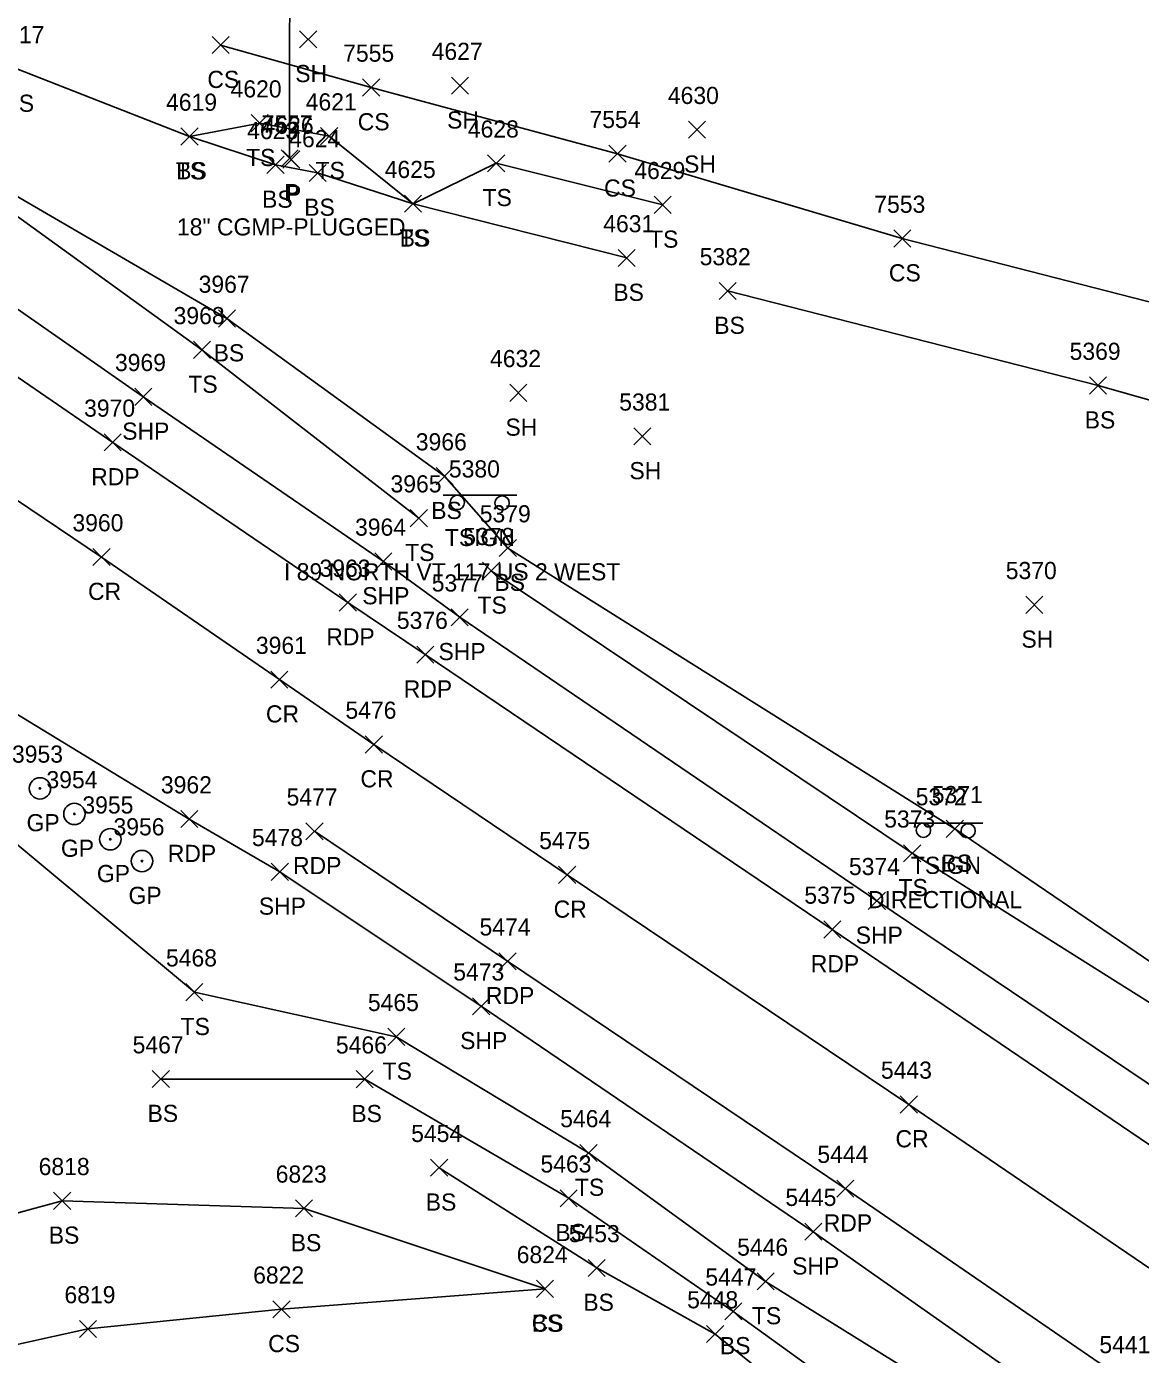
# Model space of a CAD drawing. Extents: x 1505656 to 1508446, y 700805 to 703031.
# Drawn here: x 1507341.1 to 1507471, y 701441 to 701595.9 of the extents above; entities that cross this region are included whole.
import ezdxf

# ---------------------------------------------------------------- set-up
doc = ezdxf.new("R2010")
doc.units = 0
for name, color, linetype in [('D_A', 7, 'Continuous'), ('D_C', 7, 'Continuous'), ('D_I', 7, 'Continuous'), ('D_TIC', 7, 'Continuous'), ('DCP', 7, 'Continuous'), ('L_A', 7, 'Continuous'), ('L_I', 7, 'Continuous'), ('L_TIC', 7, 'Continuous'), ('LELB', 7, 'Continuous'), ('P_A', 7, 'Continuous'), ('P_I', 7, 'Continuous'), ('P_TIC', 7, 'Continuous'), ('PET', 7, 'Continuous'), ('PRC', 7, 'Continuous'), ('PSP', 7, 'Continuous'), ('R_A', 7, 'Continuous'), ('R_I', 7, 'Continuous'), ('RGP', 7, 'Continuous'), ('S_A', 7, 'Continuous'), ('S_C', 7, 'Continuous'), ('S_I', 7, 'Continuous'), ('SSGN', 7, 'Continuous')]:
    doc.layers.add(name, color=color, linetype=linetype)

msp = doc.modelspace()

# ---------------------------------------------------------------- linework, layer by layer
at = {"layer": 'D_TIC'}
for points in [[(1507370.79, 701579.54), (1507372.79, 701581.54)], [(1507372.79, 701579.54), (1507370.79, 701581.54)], [(1507371, 701579.4), (1507373, 701581.4)], [(1507373, 701579.4), (1507371, 701581.4)]]:
    msp.add_lwpolyline(points, dxfattribs=at)
at = {"layer": 'DCP'}
msp.add_lwpolyline([(1507371.87, 701643.87), (1507371.79, 701580.54)], dxfattribs=at)
at = {"layer": 'L_TIC'}
for points in [[(1507372.96, 701593.42), (1507374.96, 701595.42)], [(1507374.96, 701593.42), (1507372.96, 701595.42)], [(1507362.75, 701592.74), (1507364.75, 701594.74)], [(1507364.75, 701592.74), (1507362.75, 701594.74)], [(1507380.3, 701587.8), (1507382.3, 701589.8)], [(1507382.3, 701587.8), (1507380.3, 701589.8)], [(1507390.67, 701588.01), (1507392.67, 701590.01)], [(1507392.67, 701588.01), (1507390.67, 701590.01)], [(1507367.31, 701583.63), (1507369.31, 701585.63)], [(1507369.31, 701583.63), (1507367.31, 701585.63)], [(1507359.12, 701582.08), (1507361.12, 701584.08)], [(1507361.12, 701582.08), (1507359.12, 701584.08)], [(1507359.12, 701582.08), (1507361.12, 701584.08)], [(1507361.12, 701582.08), (1507359.12, 701584.08)], [(1507375.41, 701582.12), (1507377.41, 701584.12)], [(1507377.41, 701582.12), (1507375.41, 701584.12)], [(1507418.31, 701582.87), (1507420.31, 701584.87)], [(1507420.31, 701582.87), (1507418.31, 701584.87)], [(1507394.89, 701578.96), (1507396.89, 701580.96)], [(1507396.89, 701578.96), (1507394.89, 701580.96)], [(1507409.03, 701580.07), (1507411.03, 701582.07)], [(1507411.03, 701580.07), (1507409.03, 701582.07)], [(1507369.14, 701578.77), (1507371.14, 701580.77)], [(1507371.14, 701578.77), (1507369.14, 701580.77)], [(1507374.06, 701577.83), (1507376.06, 701579.83)], [(1507376.06, 701577.83), (1507374.06, 701579.83)], [(1507385.19, 701574.24), (1507387.19, 701576.24)], [(1507387.19, 701574.24), (1507385.19, 701576.24)], [(1507385.19, 701574.24), (1507387.19, 701576.24)], [(1507387.19, 701574.24), (1507385.19, 701576.24)], [(1507414.31, 701574.11), (1507416.31, 701576.11)], [(1507416.31, 701574.11), (1507414.31, 701576.11)], [(1507442.25, 701570.18), (1507444.25, 701572.18)], [(1507444.25, 701570.18), (1507442.25, 701572.18)], [(1507410.11, 701567.91), (1507412.11, 701569.91)], [(1507412.11, 701567.91), (1507410.11, 701569.91)], [(1507421.88, 701564.06), (1507423.88, 701566.06)], [(1507423.88, 701564.06), (1507421.88, 701566.06)], [(1507363.48, 701560.85), (1507365.48, 701562.85)], [(1507365.48, 701560.85), (1507363.48, 701562.85)], [(1507360.57, 701557.19), (1507362.57, 701559.19)], [(1507362.57, 701557.19), (1507360.57, 701559.19)], [(1507465.09, 701553.03), (1507467.09, 701555.03)], [(1507467.09, 701553.03), (1507465.09, 701555.03)], [(1507397.48, 701552.18), (1507399.48, 701554.18)], [(1507399.48, 701552.18), (1507397.48, 701554.18)], [(1507411.94, 701547.11), (1507413.94, 701549.11)], [(1507413.94, 701547.11), (1507411.94, 701549.11)], [(1507388.87, 701542.47), (1507390.87, 701544.47)], [(1507390.87, 701542.47), (1507388.87, 701544.47)], [(1507385.87, 701537.57), (1507387.87, 701539.57)], [(1507387.87, 701537.57), (1507385.87, 701539.57)], [(1507396.24, 701534.08), (1507398.24, 701536.08)], [(1507398.24, 701534.08), (1507396.24, 701536.08)], [(1507394.3, 701531.43), (1507396.3, 701533.43)], [(1507396.3, 701531.43), (1507394.3, 701533.43)], [(1507457.66, 701527.46), (1507459.66, 701529.46)], [(1507459.66, 701527.46), (1507457.66, 701529.46)], [(1507448.38, 701501.33), (1507450.38, 701503.33)], [(1507450.38, 701501.33), (1507448.38, 701503.33)], [(1507443.4, 701498.48), (1507445.4, 701500.48)], [(1507445.4, 701498.48), (1507443.4, 701500.48)], [(1507359.68, 701482.28), (1507361.68, 701484.28)], [(1507361.68, 701482.28), (1507359.68, 701484.28)], [(1507383.23, 701477.08), (1507385.23, 701479.08)], [(1507385.23, 701477.08), (1507383.23, 701479.08)], [(1507355.78, 701472.15), (1507357.78, 701474.15)], [(1507357.78, 701472.15), (1507355.78, 701474.15)], [(1507379.55, 701472.13), (1507381.55, 701474.13)], [(1507381.55, 701472.13), (1507379.55, 701474.13)], [(1507405.66, 701463.53), (1507407.66, 701465.53)], [(1507407.66, 701463.53), (1507405.66, 701465.53)], [(1507388.23, 701461.81), (1507390.23, 701463.81)], [(1507390.23, 701461.81), (1507388.23, 701463.81)], [(1507403.35, 701458.25), (1507405.35, 701460.25)], [(1507405.35, 701458.25), (1507403.35, 701460.25)], [(1507344.26, 701457.95), (1507346.26, 701459.95)], [(1507346.26, 701457.95), (1507344.26, 701459.95)], [(1507372.48, 701457.07), (1507374.48, 701459.07)], [(1507374.48, 701457.07), (1507372.48, 701459.07)], [(1507406.61, 701450.12), (1507408.61, 701452.12)], [(1507408.61, 701450.12), (1507406.61, 701452.12)], [(1507400.59, 701447.68), (1507402.59, 701449.68)], [(1507402.59, 701447.68), (1507400.59, 701449.68)], [(1507400.59, 701447.68), (1507402.59, 701449.68)], [(1507402.59, 701447.68), (1507400.59, 701449.68)], [(1507426.31, 701448.55), (1507428.31, 701450.55)], [(1507428.31, 701448.55), (1507426.31, 701450.55)], [(1507369.84, 701445.3), (1507371.84, 701447.3)], [(1507371.84, 701445.3), (1507369.84, 701447.3)], [(1507422.54, 701445.06), (1507424.54, 701447.06)], [(1507424.54, 701445.06), (1507422.54, 701447.06)], [(1507347.27, 701443), (1507349.27, 701445)], [(1507349.27, 701443), (1507347.27, 701445)], [(1507420.42, 701442.41), (1507422.42, 701444.41)], [(1507422.42, 701442.41), (1507420.42, 701444.41)]]:
    msp.add_lwpolyline(points, dxfattribs=at)
at = {"layer": 'LELB'}
for points in [[(1507389.87, 701543.47), (1507364.48, 701561.85), (1507301.81, 701598.33), (1507262.96, 701621.17), (1507238.69, 701635.33), (1507228.62, 701642.18), (1507195.21, 701666.36), (1507195.45, 701673.67), (1507195.45, 701673.62), (1507166.37, 701693.97), (1507153.7, 701702.61), (1507143.46, 701707.63), (1507119.44, 701724.95), (1507096.28, 701741.3), (1507098.84, 701745.06), (1507084.55, 701753.38), (1507076.37, 701753.77)], [(1507247.4, 701638.91), (1507254.77, 701631.75), (1507267.97, 701626.49), (1507283.55, 701614.76), (1507308.22, 701603.82), (1507321.52, 701597.53), (1507339.98, 701590.96), (1507360.12, 701583.08), (1507370.14, 701579.77), (1507375.06, 701578.83), (1507386.19, 701575.24), (1507411.11, 701568.91)], [(1507386.87, 701538.57), (1507361.57, 701558.19), (1507324.01, 701585.32), (1507299.55, 701594.54), (1507261.37, 701618.9), (1507238.69, 701635.33)], [(1508002.64, 701414.99), (1507979.81, 701421.48), (1507944.12, 701429.96), (1507890.75, 701447.74), (1507838.58, 701464.8), (1507785.46, 701481.02), (1507746.69, 701489.76), (1507701.55, 701503.96), (1507692.53, 701505.99), (1507687.4, 701507.46), (1507675.9, 701505.41), (1507637.25, 701514.14), (1507591.55, 701528.66), (1507550.69, 701540.13), (1507511.03, 701552.01), (1507480.52, 701561.6), (1507443.25, 701571.18), (1507410.03, 701581.07), (1507381.3, 701588.8), (1507363.75, 701593.74)], [(1507360.12, 701583.08), (1507368.31, 701584.63), (1507376.41, 701583.12), (1507386.19, 701575.24), (1507395.89, 701579.96), (1507415.31, 701575.11)], [(1507494.24, 701475.49), (1507485.48, 701485.12), (1507482.34, 701502.12), (1507485.56, 701510.11), (1507495.72, 701531.95), (1507503.53, 701543.43), (1507466.09, 701554.03), (1507422.88, 701565.06)], [(1507397.24, 701535.08), (1507389.87, 701543.47)], [(1507596.81, 701404.28), (1507581.31, 701416.71), (1507546.65, 701439.08), (1507526.39, 701451.36), (1507494.24, 701475.49), (1507483.92, 701478.85), (1507449.38, 701502.33), (1507397.24, 701535.08)], [(1507585.56, 701401.05), (1507575.59, 701409.05), (1507541.66, 701431.82), (1507522.44, 701445.53), (1507489.85, 701469.54), (1507483.43, 701474.91), (1507444.4, 701499.48), (1507395.3, 701532.43)], [(1507331.15, 701507.85), (1507360.68, 701483.28)], [(1507556.64, 701327.28), (1507557.61, 701343.99), (1507554.26, 701358.96), (1507537.42, 701375.15), (1507498.82, 701402.26), (1507464.49, 701426.4), (1507427.31, 701449.55), (1507406.66, 701464.53), (1507384.23, 701478.08), (1507360.68, 701483.28)], [(1507257.2, 701477.1), (1507295.53, 701466.28), (1507314.2, 701450.53), (1507345.26, 701458.95), (1507373.48, 701458.07), (1507401.59, 701448.68)], [(1507552.22, 701329.86), (1507547.62, 701348.23), (1507546.96, 701358.62), (1507528.89, 701372.8), (1507497.02, 701400), (1507459.73, 701419.9), (1507423.54, 701446.06), (1507404.35, 701459.25), (1507380.55, 701473.13), (1507356.78, 701473.15)], [(1507253.51, 701468.63), (1507288.66, 701454.6), (1507310.43, 701435.66), (1507348.27, 701444), (1507370.84, 701446.3), (1507401.59, 701448.68)], [(1507544.85, 701333.56), (1507537.16, 701349.93), (1507537.38, 701358.92), (1507523.47, 701367.02), (1507491.66, 701393.21), (1507456.99, 701414.76), (1507421.42, 701443.41), (1507407.61, 701451.12), (1507389.23, 701462.81)]]:
    msp.add_lwpolyline(points, dxfattribs=at)
at = {"layer": 'P_TIC'}
for points in [[(1507353.73, 701551.72), (1507355.73, 701553.72)], [(1507355.73, 701551.72), (1507353.73, 701553.72)], [(1507350.16, 701546.4), (1507352.16, 701548.4)], [(1507352.16, 701546.4), (1507350.16, 701548.4)], [(1507348.85, 701533.03), (1507350.85, 701535.03)], [(1507350.85, 701533.03), (1507348.85, 701535.03)], [(1507381.73, 701532.52), (1507383.73, 701534.52)], [(1507383.73, 701532.52), (1507381.73, 701534.52)], [(1507377.59, 701527.73), (1507379.59, 701529.73)], [(1507379.59, 701527.73), (1507377.59, 701529.73)], [(1507390.63, 701526.01), (1507392.63, 701528.01)], [(1507392.63, 701526.01), (1507390.63, 701528.01)], [(1507386.62, 701521.65), (1507388.62, 701523.65)], [(1507388.62, 701521.65), (1507386.62, 701523.65)], [(1507369.6, 701518.74), (1507371.6, 701520.74)], [(1507371.6, 701518.74), (1507369.6, 701520.74)], [(1507380.62, 701511.17), (1507382.62, 701513.17)], [(1507382.62, 701511.17), (1507380.62, 701513.17)], [(1507359.09, 701502.47), (1507361.09, 701504.47)], [(1507361.09, 701502.47), (1507359.09, 701504.47)], [(1507373.7, 701501.05), (1507375.7, 701503.05)], [(1507375.7, 701501.05), (1507373.7, 701503.05)], [(1507369.66, 701496.32), (1507371.66, 701498.32)], [(1507371.66, 701496.32), (1507369.66, 701498.32)], [(1507403.16, 701495.97), (1507405.16, 701497.97)], [(1507405.16, 701495.97), (1507403.16, 701497.97)], [(1507439.29, 701492.94), (1507441.29, 701494.94)], [(1507441.29, 701492.94), (1507439.29, 701494.94)], [(1507434.09, 701489.6), (1507436.09, 701491.6)], [(1507436.09, 701489.6), (1507434.09, 701491.6)], [(1507396.2, 701485.89), (1507398.2, 701487.89)], [(1507398.2, 701485.89), (1507396.2, 701487.89)], [(1507393.14, 701480.64), (1507395.14, 701482.64)], [(1507395.14, 701480.64), (1507393.14, 701482.64)], [(1507443.02, 701469.19), (1507445.02, 701471.19)], [(1507445.02, 701469.19), (1507443.02, 701471.19)], [(1507435.61, 701459.37), (1507437.61, 701461.37)], [(1507437.61, 701459.37), (1507435.61, 701461.37)], [(1507431.87, 701454.35), (1507433.87, 701456.35)], [(1507433.87, 701454.35), (1507431.87, 701456.35)]]:
    msp.add_lwpolyline(points, dxfattribs=at)
at = {"layer": 'PET'}
for points in [[(1507378.59, 701528.73), (1507351.16, 701547.4), (1507314.88, 701572.26), (1507294.11, 701586.22), (1507256.28, 701612.27), (1507223.68, 701635.26), (1507191.52, 701659.04), (1507185.41, 701663.24), (1507156.11, 701681.55), (1507130.98, 701696.87), (1507096.16, 701719.91), (1507064.32, 701737.66), (1507038.74, 701752.58), (1507011.47, 701766.55), (1506986.91, 701777.55), (1506973.48, 701783.54), (1506938.47, 701797.09), (1506905.53, 701808.93), (1506877.58, 701817.04), (1506846.41, 701824.78), (1506827.4, 701828.82), (1506804.26, 701834.04), (1506782.21, 701837.88), (1506762.06, 701842.49)], [(1507210, 701607.35), (1507255.64, 701576.09), (1507286.41, 701554.16), (1507313.14, 701536.08), (1507337.33, 701517.31), (1507360.09, 701503.47)], [(1507387.62, 701522.65), (1507378.59, 701528.73)], [(1507628.51, 701359.69), (1507604.05, 701376.49), (1507573.51, 701397.18), (1507535.4, 701422.88), (1507481.89, 701458.82), (1507435.09, 701490.6), (1507387.62, 701522.65)], [(1507650.58, 701314.23), (1507605.27, 701346.09), (1507547.72, 701383.86), (1507511.59, 701409.01), (1507468.93, 701438.18), (1507436.61, 701460.37), (1507397.2, 701486.89), (1507374.7, 701502.05)]]:
    msp.add_lwpolyline(points, dxfattribs=at)
at = {"layer": 'PRC'}
for points in [[(1507221.62, 701620.55), (1507265.06, 701591.23), (1507297.41, 701569.41), (1507322.82, 701552.21), (1507349.85, 701534.03), (1507370.6, 701519.74)], [(1507381.62, 701512.17), (1507370.6, 701519.74)], [(1507656.71, 701325.12), (1507611.54, 701355.7), (1507570.54, 701383.97), (1507541.91, 701403.48), (1507511.11, 701424.43), (1507476, 701448.42), (1507444.02, 701470.19), (1507404.16, 701496.97), (1507381.62, 701512.17)]]:
    msp.add_lwpolyline(points, dxfattribs=at)
at = {"layer": 'PSP'}
for points in [[(1507382.73, 701533.52), (1507354.73, 701552.72), (1507319.48, 701577.3), (1507297.42, 701590.8), (1507259.58, 701616.5), (1507227.21, 701639.99), (1507194.31, 701663.43), (1507160.97, 701687.92), (1507137.4, 701705.45), (1507106.21, 701729.57), (1507075.31, 701752.35), (1507059.92, 701763.53), (1507033.38, 701782.57), (1507002.26, 701805.46), (1506985.6, 701817.32), (1506980.95, 701818.44), (1506978.16, 701819.92), (1506965.68, 701828.93)], [(1507391.63, 701527.01), (1507382.73, 701533.52)], [(1507630.66, 701364.45), (1507607.41, 701380.86), (1507575.86, 701401.66), (1507537.87, 701427.72), (1507485.39, 701463.56), (1507440.29, 701493.94), (1507391.63, 701527.01)], [(1507370.66, 701497.32), (1507360.09, 701503.47)], [(1507544.33, 701378.59), (1507503.06, 701407.32), (1507465.55, 701432.37), (1507432.87, 701455.35), (1507394.14, 701481.64), (1507370.66, 701497.32)]]:
    msp.add_lwpolyline(points, dxfattribs=at)
at = {"layer": 'RGP'}
for p, q in [((1507342.67, 701507.05), (1507342.67, 701507.05)), ((1507346.69, 701504.07), (1507346.69, 701504.07)), ((1507350.88, 701501.12), (1507350.88, 701501.12)), ((1507354.57, 701498.57), (1507354.57, 701498.57))]:
    msp.add_line(p, q, dxfattribs=at)
for centre, radius in [((1507342.67, 701507.05), 1.25), ((1507342.67, 701507.05), 0.0833), ((1507346.69, 701504.07), 1.25), ((1507346.69, 701504.07), 0.0833), ((1507350.88, 701501.12), 1.25), ((1507350.88, 701501.12), 0.0833), ((1507354.57, 701498.57), 1.25), ((1507354.57, 701498.57), 0.0833)]:
    msp.add_circle(centre, radius, dxfattribs=at)
at = {"layer": 'SSGN'}
for p, q in [((1507389.7, 701541.23), (1507398.3, 701541.23)), ((1507393.72, 701540.33), (1507393.72, 701540.33)), ((1507444.06, 701503.01), (1507452.66, 701503.01)), ((1507448.09, 701502.1), (1507448.09, 701502.1))]:
    msp.add_line(p, q, dxfattribs=at)
for centre in [(1507391.36, 701540.4), (1507396.58, 701540.33), (1507445.72, 701502.17), (1507450.94, 701502.1)]:
    msp.add_circle(centre, 0.833, dxfattribs=at)

# ---------------------------------------------------------------- texts
at = {"layer": 'D_A'}
for p in [(1507371.17, 701575.54), (1507371.38, 701575.4)]:
    msp.add_text('P', height=2, dxfattribs=at).set_placement(p)
at = {"layer": 'D_C'}
msp.add_text('18" CGMP-PLUGGED', height=2, dxfattribs=at).set_placement((1507358.65, 701571.54))
at = {"layer": 'D_I'}
for s, p in [('7557', (1507368.53, 701583.54)), ('4626', (1507368.64, 701583.4))]:
    msp.add_text(s, height=2, dxfattribs=at).set_placement(p)
at = {"layer": 'L_A'}
for s, p in [('CS', (1507362.2, 701588.74)), ('SH', (1507372.45, 701589.42)), ('BS', (1507338.42, 701585.96)), ('CS', (1507379.74, 701583.8)), ('SH', (1507390.16, 701584.01)), ('TS', (1507366.72, 701579.63)), ('SH', (1507417.8, 701578.87)), ('TS', (1507358.53, 701578.08)), ('BS', (1507358.56, 701578.08)), ('TS', (1507374.82, 701578.12)), ('CS', (1507408.47, 701576.07)), ('BS', (1507368.58, 701574.77)), ('TS', (1507394.3, 701574.96)), ('BS', (1507373.5, 701573.83)), ('TS', (1507384.6, 701570.24)), ('BS', (1507384.63, 701570.24)), ('TS', (1507413.72, 701570.11)), ('CS', (1507441.69, 701566.18)), ('BS', (1507409.55, 701563.91)), ('BS', (1507421.32, 701560.06)), ('BS', (1507362.93, 701556.85)), ('TS', (1507359.98, 701553.19)), ('SH', (1507396.97, 701548.18)), ('BS', (1507464.53, 701549.03)), ('SH', (1507411.43, 701543.11)), ('BS', (1507388.31, 701538.47)), ('TS', (1507385.28, 701533.57)), ('BS', (1507395.68, 701530.08)), ('TS', (1507393.71, 701527.43)), ('SH', (1507457.15, 701523.46)), ('BS', (1507447.82, 701497.33)), ('TS', (1507442.81, 701494.48)), ('TS', (1507359.08, 701478.28)), ('TS', (1507382.64, 701473.08)), ('BS', (1507355.22, 701468.15)), ('BS', (1507378.99, 701468.13)), ('TS', (1507405.07, 701459.53)), ('BS', (1507387.67, 701457.81)), ('BS', (1507343.7, 701453.95)), ('BS', (1507402.79, 701454.25)), ('BS', (1507371.92, 701453.07)), ('BS', (1507406.05, 701446.12)), ('TS', (1507425.72, 701444.55)), ('CS', (1507400.03, 701443.68)), ('BS', (1507400.03, 701443.68)), ('CS', (1507369.29, 701441.3)), ('BS', (1507421.98, 701441.06))]:
    msp.add_text(s, height=2, dxfattribs=at).set_placement(p)
at = {"layer": 'L_I'}
for s, p in [('4617', (1507337.24, 701593.96)), ('7555', (1507378.04, 701591.8)), ('4627', (1507388.36, 701592.01)), ('4620', (1507364.91, 701587.63)), ('4630', (1507415.91, 701586.87)), ('4619', (1507357.38, 701586.08)), ('4619', (1507357.38, 701586.08)), ('4621', (1507373.67, 701586.12)), ('7554', (1507406.77, 701584.07)), ('4623', (1507366.84, 701582.77)), ('4628', (1507392.58, 701582.96)), ('4624', (1507371.75, 701581.83)), ('4625', (1507382.88, 701578.24)), ('4625', (1507382.88, 701578.24)), ('4629', (1507412, 701578.11)), ('7553', (1507439.99, 701574.18)), ('4631', (1507408.37, 701571.91)), ('5382', (1507419.62, 701568.06)), ('3967', (1507361.18, 701564.85)), ('3968', (1507358.26, 701561.19)), ('4632', (1507395.17, 701556.18)), ('5369', (1507462.77, 701557.03)), ('5381', (1507410.24, 701551.11)), ('3966', (1507386.51, 701546.47)), ('3965', (1507383.56, 701541.57)), ('5379', (1507393.97, 701538.08)), ('5378', (1507392.04, 701535.43)), ('5370', (1507455.32, 701531.46)), ('5371', (1507446.69, 701505.33)), ('5373', (1507441.14, 701502.48)), ('5468', (1507357.37, 701486.28)), ('5465', (1507380.92, 701481.08)), ('5467', (1507353.48, 701476.15)), ('5466', (1507377.19, 701476.13)), ('5464', (1507403.35, 701467.53)), ('5454', (1507385.97, 701465.81)), ('6818', (1507342.52, 701461.95)), ('5463', (1507401.05, 701462.25)), ('6823', (1507370.17, 701461.07)), ('5453', (1507404.35, 701454.12)), ('5446', (1507423.99, 701452.55)), ('6824', (1507398.28, 701451.68)), ('6824', (1507398.28, 701451.68)), ('6822', (1507367.54, 701449.3)), ('5447', (1507420.28, 701449.06)), ('6819', (1507345.53, 701447)), ('5448', (1507418.16, 701446.41))]:
    msp.add_text(s, height=2, dxfattribs=at).set_placement(p)
at = {"layer": 'P_A'}
for s, p in [('SHP', (1507352.27, 701547.72)), ('RDP', (1507348.65, 701542.4)), ('CR', (1507348.28, 701529.03)), ('SHP', (1507380.27, 701528.52)), ('RDP', (1507376.07, 701523.73)), ('SHP', (1507389.16, 701522.01)), ('RDP', (1507385.1, 701517.65)), ('CR', (1507369.03, 701514.74)), ('CR', (1507380.05, 701507.17)), ('RDP', (1507357.58, 701498.47)), ('RDP', (1507372.19, 701497.05)), ('SHP', (1507368.2, 701492.32)), ('CR', (1507402.59, 701491.97)), ('SHP', (1507437.82, 701488.94)), ('RDP', (1507432.58, 701485.6)), ('RDP', (1507394.69, 701481.89)), ('SHP', (1507391.68, 701476.64)), ('CR', (1507442.46, 701465.19)), ('RDP', (1507434.09, 701455.37)), ('SHP', (1507430.41, 701450.35))]:
    msp.add_text(s, height=2, dxfattribs=at).set_placement(p)
at = {"layer": 'P_I'}
for s, p in [('3969', (1507351.42, 701555.72)), ('3970', (1507347.82, 701550.4)), ('3960', (1507346.46, 701537.03)), ('3964', (1507379.42, 701536.52)), ('3963', (1507375.28, 701531.73)), ('5377', (1507388.37, 701530.01)), ('5376', (1507384.3, 701525.65)), ('3961', (1507367.86, 701522.74)), ('5476', (1507378.3, 701515.17)), ('3962', (1507356.78, 701506.47)), ('5477', (1507371.44, 701505.05)), ('5478', (1507367.4, 701500.32)), ('5475', (1507400.9, 701499.97)), ('5374', (1507437.03, 701496.94)), ('5375', (1507431.83, 701493.6)), ('5474', (1507393.94, 701489.89)), ('5473', (1507390.88, 701484.64)), ('5443', (1507440.76, 701473.19)), ('5444', (1507433.35, 701463.37)), ('5445', (1507429.62, 701458.35)), ('5441', (1507466.24, 701441.18))]:
    msp.add_text(s, height=2, dxfattribs=at).set_placement(p)
at = {"layer": 'R_A'}
for p in [(1507341.11, 701502.05), (1507345.12, 701499.07), (1507349.31, 701496.12), (1507353, 701493.57)]:
    msp.add_text('GP', height=2, dxfattribs=at).set_placement(p)
at = {"layer": 'R_I'}
for s, p in [('3953', (1507339.41, 701510.05)), ('3954', (1507343.43, 701507.07)), ('3955', (1507347.62, 701504.12)), ('3956', (1507351.25, 701501.57))]:
    msp.add_text(s, height=2, dxfattribs=at).set_placement(p)
at = {"layer": 'S_A'}
for p in [(1507389.9, 701535.31), (1507444.26, 701497.08)]:
    msp.add_text('TSIGN', height=2, dxfattribs=at).set_placement(p)
at = {"layer": 'S_C'}
for s, p in [('I 89 NORTH VT 117 US 2 WEST', (1507371.13, 701531.31)), ('DIRECTIONAL', (1507439.25, 701493.08))]:
    msp.add_text(s, height=2, dxfattribs=at).set_placement(p)
at = {"layer": 'S_I'}
for s, p in [('5380', (1507390.37, 701543.31)), ('5372', (1507444.82, 701505.08))]:
    msp.add_text(s, height=2, dxfattribs=at).set_placement(p)

doc.saveas('drawing.dxf')
